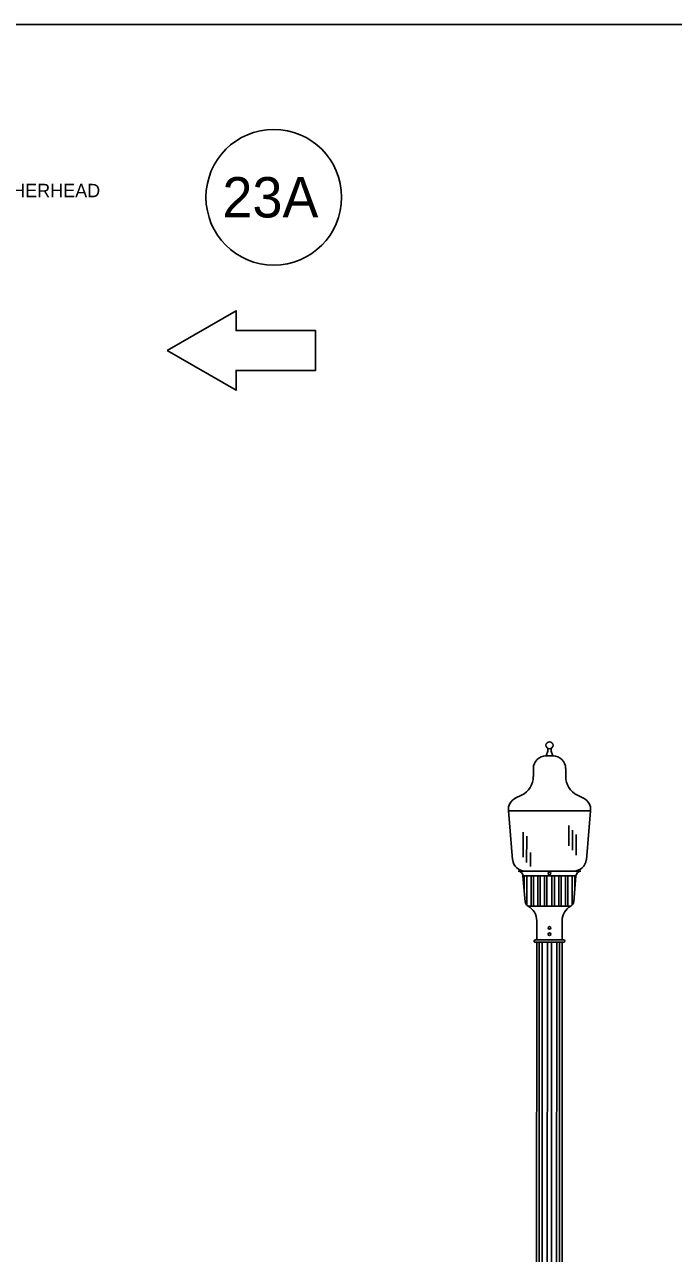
# Model space of a CAD drawing. Extents: x 99968 to 128667, y 90163 to 102182.
# Drawn here: x 121413 to 121992, y 91267 to 92363 of the extents above; entities that cross this region are included whole.
import ezdxf

# ---------------------------------------------------------------- set-up
doc = ezdxf.new("R2010")
doc.units = 0
for name, color, linetype in [('Border Organizer Shape', 7, 'Continuous'), ('Border Prelim Stamp', 7, 'Continuous'), ('RD Standard Plans Active', 7, 'Continuous')]:
    doc.layers.add(name, color=color, linetype=linetype)

msp = doc.modelspace()

# ---------------------------------------------------------------- linework, layer by layer
at = {"layer": 'Border Organizer Shape'}
msp.add_lwpolyline([(120413.5, 90163.3), (123613.2, 90163.3), (123613.2, 92362.9), (120413.5, 92362.9)], close=True, dxfattribs=at)
at = {"layer": 'Border Prelim Stamp'}
msp.add_lwpolyline([(121540.5, 92072.2), (121601.9, 92107.6), (121601.9, 92089.9), (121672.9, 92089.9), (121672.9, 92054.4), (121601.9, 92054.4), (121601.9, 92036.7)], close=True, dxfattribs=at)
msp.add_ellipse((121635.6, 92208.8), major_axis=(-60.5, 0), ratio=0.999984, dxfattribs=at)
at = {"layer": 'RD Standard Plans Active'}
for p, q in [((121878.4, 91710.6), (121884.8, 91710.6)), ((121878.4, 91710.6), (121884.8, 91710.6)), ((121867.2, 91692.2), (121867.2, 91699.3)), ((121867.2, 91692.2), (121867.2, 91699.3)), ((121896.1, 91699.3), (121896.1, 91692.2)), ((121896.1, 91699.3), (121896.1, 91692.2)), ((121851.1, 91672.7), (121856.6, 91675.4)), ((121851.1, 91672.7), (121856.6, 91675.4)), ((121906.6, 91675.4), (121912, 91672.7)), ((121906.6, 91675.4), (121912, 91672.7)), ((121848.7, 91617.9), (121844.9, 91661.7)), ((121918.3, 91661.6), (121844.9, 91661.6)), ((121918.3, 91661.6), (121844.9, 91661.6)), ((121914.5, 91617.9), (121918.3, 91661.6)), ((121858, 91642.6), (121858, 91620.3)), ((121861.3, 91639), (121861.2, 91615.5)), ((121898.8, 91648.3), (121898.8, 91630.2)), ((121902.1, 91644.4), (121902.1, 91626.5)), ((121905.5, 91640.4), (121905.5, 91622)), ((121864.8, 91624.2), (121864.8, 91611.8)), ((121853.5, 91607.7), (121909.7, 91607.6)), ((121857.9, 91603.6), (121905.2, 91603.5)), ((121859.1, 91590.7), (121859.1, 91603.6)), ((121861.3, 91577.4), (121861.3, 91603.6)), ((121865.1, 91576.5), (121865.1, 91603.6)), ((121867.3, 91576.5), (121867.3, 91603.6)), ((121871.1, 91576.5), (121871.1, 91603.6)), ((121873.3, 91576.5), (121873.3, 91603.6)), ((121877.1, 91576.5), (121877.1, 91603.6)), ((121879.3, 91576.5), (121879.3, 91603.6)), ((121883.8, 91576.5), (121883.8, 91603.5)), ((121886.1, 91576.5), (121886.1, 91603.5)), ((121889.8, 91576.5), (121889.8, 91603.5)), ((121892.1, 91576.5), (121892.1, 91603.5)), ((121895.8, 91576.5), (121895.8, 91603.5)), ((121898.1, 91576.5), (121898.1, 91603.5)), ((121901.8, 91577.4), (121901.8, 91603.5)), ((121904.1, 91590.6), (121904.1, 91603.5)), ((121900.7, 91576.5), (121862.5, 91576.5)), ((121870.2, 91546.4), (121870.2, 91563.4)), ((121892.9, 91546.4), (121892.9, 91563.4)), ((121869, 91546.4), (121894.1, 91546.4)), ((121869, 91544.2), (121894.1, 91544.2)), ((121869, 91544.2), (121894.1, 91544.2)), ((121870.2, 91544.2), (121869.9, 90749.7)), ((121872.3, 90749.7), (121872.5, 91544.2)), ((121874.8, 90749.7), (121875.1, 91544.2)), ((121879.4, 90749.7), (121879.7, 91544.2)), ((121883.2, 90749.7), (121883.5, 91544.2)), ((121887.8, 90749.7), (121888.1, 91544.2)), ((121890.4, 90749.7), (121890.6, 91544.2)), ((121893, 91544.2), (121892.7, 90749.7))]:
    msp.add_line(p, q, dxfattribs=at)
for points in [[(121880, 91717.3), (121880, 91714.7), (121878.5, 91710.6)], [(121883.2, 91717.3), (121883.2, 91714.7), (121884.7, 91710.6)], [(121860, 91580.4), (121857.9, 91603.6)], [(121903.2, 91580.3), (121905.2, 91603.5)]]:
    msp.add_lwpolyline(points, dxfattribs=at)
for centre, radius in [((121881.6, 91720), 3.13), ((121881.6, 91605.7), 1.19), ((121881.6, 91557), 1.19), ((121881.6, 91551.4), 1.19)]:
    msp.add_circle(centre, radius, dxfattribs=at)
for centre, radius, start, end in [((121878.4, 91699.3), 11.2, 89.9775, 179.9775), ((121878.4, 91699.3), 11.2, 89.9775, 179.9775), ((121884.8, 91699.3), 11.2, 359.9775, 89.9775), ((121884.8, 91699.3), 11.2, 359.9775, 89.9775), ((121848.4, 91692.2), 18.7, 296.0078, 359.9775), ((121848.4, 91692.2), 18.7, 296.0078, 359.9775), ((121914.8, 91692.2), 18.7, 179.9775, 243.9471), ((121914.8, 91692.2), 18.7, 179.9775, 243.9471), ((121856.1, 91662.6), 11.2, 116.0078, 185.0021), ((121856.1, 91662.6), 11.2, 116.0078, 185.0021), ((121907.1, 91662.6), 11.2, 354.9529, 63.9471), ((121907.1, 91662.6), 11.2, 354.9529, 63.9471), ((121859.9, 91618.9), 11.2, 185.0021, 269.9775), ((121903.2, 91618.9), 11.2, 269.9775, 354.9529), ((121853.5, 91603.2), 4.5, 4.9906, 89.9775), ((121909.7, 91603.1), 4.5, 89.9775, 174.9644), ((121864.8, 91580.8), 4.87, 184.9906, 241.1366), ((121855.2, 91563.4), 15, 359.9775, 61.1323), ((121907.9, 91563.4), 15, 118.8227, 179.9775), ((121898.3, 91580.8), 4.87, 298.8184, 354.9644), ((121869, 91545.3), 1.12, 89.9775, 269.9775), ((121894.1, 91545.3), 1.12, 269.9775, 89.9775)]:
    msp.add_arc(centre, radius, start, end, dxfattribs=at)

# ---------------------------------------------------------------- texts
at = {"layer": 'Border Prelim Stamp'}
msp.add_text('23A', height=36, dxfattribs=at).set_placement((121589.8, 92190.8))
at = {"layer": 'RD Standard Plans Active'}
msp.add_text(' SERVICE ENTRANCE WEATHERHEAD', height=12, dxfattribs=at).set_placement((121183.8, 92208.8))

doc.saveas('drawing.dxf')
